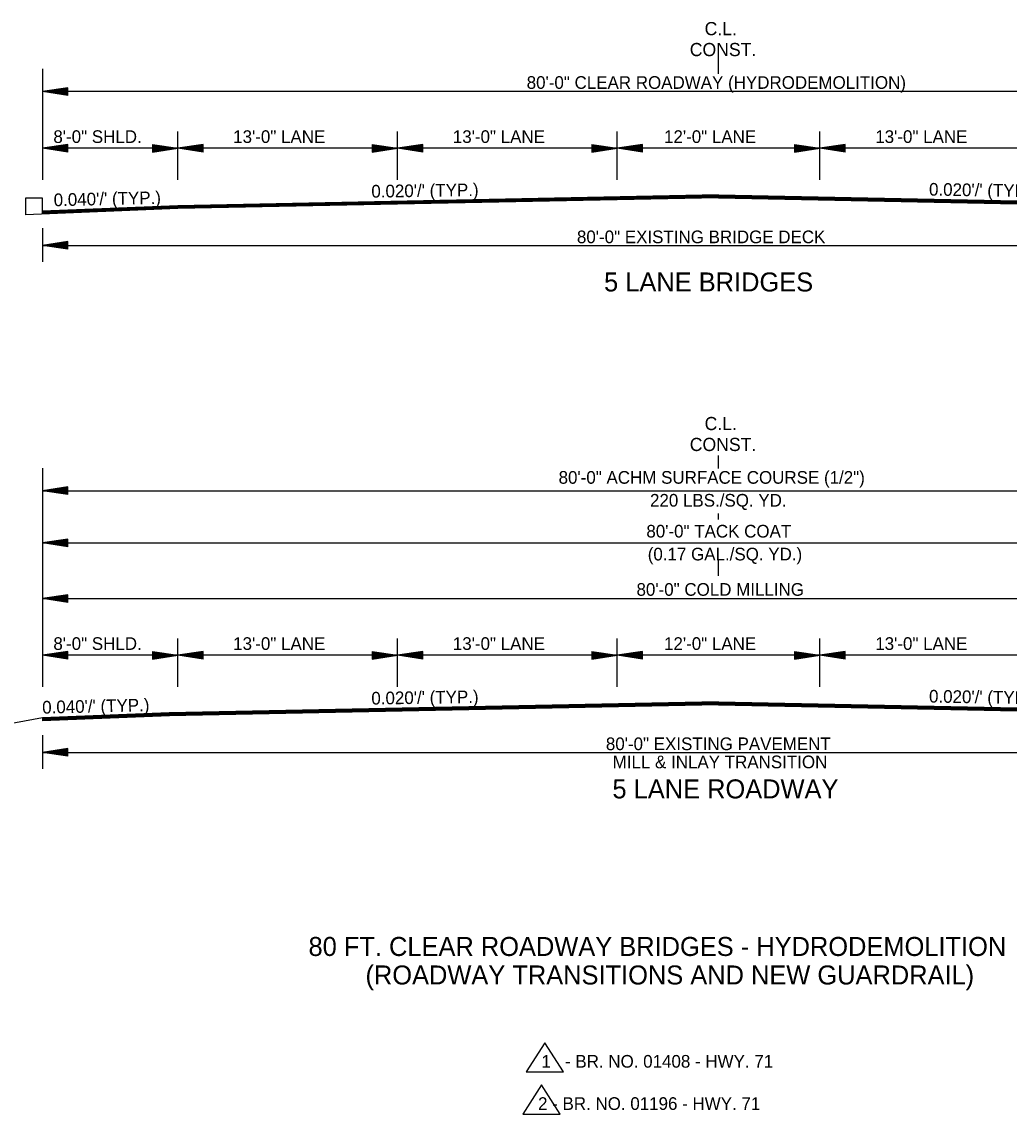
# Model space of a CAD drawing. Extents: x 542112 to 1930787, y -1968972 to 596640.
# Drawn here: x 544304 to 544888, y -1948133 to -1947487 of the extents above; entities that cross this region are included whole.
import ezdxf

# ---------------------------------------------------------------- set-up
doc = ezdxf.new("R2010")
doc.units = 0
doc.layers.add('R_Border', color=7, linetype='Continuous')
doc.layers.add('R_Draft', color=7, linetype='Continuous')

msp = doc.modelspace()

# ---------------------------------------------------------------- linework, layer by layer
at = {"layer": 'R_Border'}
for p, q in [((544315.93, -1947590.92), (544305.76, -1947590.92)), ((544305.76, -1947590.92), (544305.76, -1947600.74)), ((544315.93, -1947600.33), (544315.93, -1947590.92)), ((544613.21, -1948090.71), (544602.17, -1948108.01)), ((544624.25, -1948108.01), (544613.21, -1948090.71)), ((544602.17, -1948108.01), (544624.25, -1948108.01)), ((544611.21, -1948115.71), (544600.17, -1948133.01)), ((544622.25, -1948133.01), (544611.21, -1948115.71)), ((544600.17, -1948133.01), (544622.25, -1948133.01))]:
    msp.add_line(p, q, dxfattribs=at)
at = {"layer": 'R_Draft'}
for p, q in [((544715.93, -1947514.5), (544715.93, -1947505.2)), ((544715.93, -1947517.31), (544715.93, -1947509.46)), ((544315.93, -1947514.45), (544315.93, -1947580.11)), ((544330.93, -1947525.67), (544315.93, -1947527.92)), ((544330.93, -1947530.17), (544315.93, -1947527.92)), ((545115.93, -1947527.92), (544315.93, -1947527.92)), ((544330.93, -1947526.04), (544318.43, -1947527.92)), ((544330.93, -1947529.79), (544318.43, -1947527.92)), ((544330.93, -1947526.42), (544321.01, -1947527.92)), ((544330.93, -1947529.41), (544321.01, -1947527.92)), ((544330.93, -1947526.8), (544323.51, -1947527.92)), ((544330.93, -1947529.03), (544323.51, -1947527.92)), ((544330.93, -1947527.18), (544326.05, -1947527.92)), ((544330.93, -1947528.64), (544326.05, -1947527.92)), ((544330.93, -1947527.56), (544328.56, -1947527.92)), ((544330.93, -1947528.27), (544328.56, -1947527.92)), ((544330.93, -1947530.17), (544330.93, -1947525.67)), ((544395.93, -1947580.11), (544395.93, -1947551.56)), ((544525.93, -1947580.11), (544525.93, -1947551.56)), ((544655.93, -1947580.11), (544655.93, -1947551.56)), ((544775.93, -1947580.11), (544775.93, -1947551.56)), ((544330.93, -1947559.2), (544315.93, -1947561.45)), ((544330.93, -1947559.58), (544318.43, -1947561.45)), ((544330.93, -1947559.96), (544321.01, -1947561.45)), ((544330.93, -1947560.34), (544323.51, -1947561.45)), ((544330.93, -1947560.72), (544326.05, -1947561.45)), ((544330.93, -1947561.1), (544328.56, -1947561.45)), ((544330.93, -1947563.7), (544330.93, -1947559.2)), ((544380.93, -1947559.2), (544395.93, -1947561.45)), ((544380.93, -1947559.2), (544380.93, -1947563.7)), ((544380.93, -1947559.58), (544393.42, -1947561.45)), ((544380.93, -1947559.96), (544390.84, -1947561.45)), ((544380.93, -1947560.34), (544388.35, -1947561.45)), ((544380.93, -1947560.73), (544385.8, -1947561.45)), ((544380.93, -1947561.1), (544383.3, -1947561.45)), ((544410.93, -1947559.2), (544395.93, -1947561.45)), ((544410.93, -1947559.58), (544398.43, -1947561.45)), ((544410.93, -1947559.96), (544401.01, -1947561.45)), ((544410.93, -1947560.34), (544403.51, -1947561.45)), ((544410.93, -1947560.72), (544406.05, -1947561.45)), ((544410.93, -1947561.1), (544408.56, -1947561.45)), ((544410.93, -1947563.7), (544410.93, -1947559.2)), ((544510.93, -1947559.2), (544525.93, -1947561.45)), ((544510.93, -1947559.2), (544510.93, -1947563.7)), ((544510.93, -1947559.58), (544523.42, -1947561.45)), ((544510.93, -1947559.96), (544520.84, -1947561.45)), ((544510.93, -1947560.34), (544518.35, -1947561.45)), ((544510.93, -1947560.73), (544515.8, -1947561.45)), ((544510.93, -1947561.1), (544513.3, -1947561.45)), ((544540.93, -1947559.2), (544525.93, -1947561.45)), ((544540.93, -1947559.58), (544528.43, -1947561.45)), ((544540.93, -1947559.96), (544531.01, -1947561.45)), ((544540.93, -1947560.34), (544533.51, -1947561.45)), ((544540.93, -1947560.72), (544536.05, -1947561.45)), ((544540.93, -1947561.1), (544538.56, -1947561.45)), ((544540.93, -1947563.7), (544540.93, -1947559.2)), ((544640.93, -1947559.2), (544655.93, -1947561.45)), ((544640.93, -1947559.2), (544640.93, -1947563.7)), ((544640.93, -1947559.58), (544653.42, -1947561.45)), ((544640.93, -1947559.96), (544650.84, -1947561.45)), ((544640.93, -1947560.34), (544648.35, -1947561.45)), ((544640.93, -1947560.73), (544645.8, -1947561.45)), ((544640.93, -1947561.1), (544643.3, -1947561.45)), ((544670.93, -1947559.2), (544655.93, -1947561.45)), ((544670.93, -1947559.58), (544658.43, -1947561.45)), ((544670.93, -1947559.96), (544661.01, -1947561.45)), ((544670.93, -1947560.34), (544663.51, -1947561.45)), ((544670.93, -1947560.72), (544666.05, -1947561.45)), ((544670.93, -1947561.1), (544668.56, -1947561.45)), ((544670.93, -1947563.7), (544670.93, -1947559.2)), ((544760.93, -1947559.2), (544775.93, -1947561.45)), ((544760.93, -1947559.2), (544760.93, -1947563.7)), ((544760.93, -1947559.58), (544773.42, -1947561.45)), ((544760.93, -1947559.96), (544770.84, -1947561.45)), ((544760.93, -1947560.34), (544768.35, -1947561.45)), ((544760.93, -1947560.73), (544765.8, -1947561.45)), ((544760.93, -1947561.1), (544763.3, -1947561.45)), ((544790.93, -1947559.2), (544775.93, -1947561.45)), ((544790.93, -1947559.58), (544778.43, -1947561.45)), ((544790.93, -1947559.96), (544781.01, -1947561.45)), ((544790.93, -1947560.34), (544783.51, -1947561.45)), ((544790.93, -1947560.72), (544786.05, -1947561.45)), ((544790.93, -1947561.1), (544788.56, -1947561.45)), ((544790.93, -1947563.7), (544790.93, -1947559.2)), ((544395.93, -1947561.45), (544315.93, -1947561.45)), ((544330.93, -1947563.7), (544315.93, -1947561.45)), ((544330.93, -1947563.33), (544318.43, -1947561.45)), ((544330.93, -1947562.95), (544321.01, -1947561.45)), ((544330.93, -1947562.57), (544323.51, -1947561.45)), ((544330.93, -1947562.18), (544326.05, -1947561.45)), ((544330.93, -1947561.81), (544328.56, -1947561.45)), ((544380.93, -1947563.7), (544395.93, -1947561.45)), ((544380.93, -1947562.19), (544385.8, -1947561.45)), ((544380.93, -1947562.95), (544390.84, -1947561.45)), ((544380.93, -1947563.33), (544393.42, -1947561.45)), ((544380.93, -1947562.57), (544388.35, -1947561.45)), ((544380.93, -1947561.81), (544383.3, -1947561.45)), ((544525.93, -1947561.45), (544395.93, -1947561.45)), ((544410.93, -1947563.7), (544395.93, -1947561.45)), ((544410.93, -1947563.33), (544398.43, -1947561.45)), ((544410.93, -1947562.95), (544401.01, -1947561.45)), ((544410.93, -1947562.57), (544403.51, -1947561.45)), ((544410.93, -1947562.18), (544406.05, -1947561.45)), ((544410.93, -1947561.81), (544408.56, -1947561.45)), ((544510.93, -1947563.7), (544525.93, -1947561.45)), ((544510.93, -1947562.19), (544515.8, -1947561.45)), ((544510.93, -1947562.95), (544520.84, -1947561.45)), ((544510.93, -1947563.33), (544523.42, -1947561.45)), ((544510.93, -1947562.57), (544518.35, -1947561.45)), ((544510.93, -1947561.81), (544513.3, -1947561.45)), ((544655.93, -1947561.45), (544525.93, -1947561.45)), ((544540.93, -1947563.7), (544525.93, -1947561.45)), ((544540.93, -1947563.33), (544528.43, -1947561.45)), ((544540.93, -1947562.95), (544531.01, -1947561.45)), ((544540.93, -1947562.57), (544533.51, -1947561.45)), ((544540.93, -1947562.18), (544536.05, -1947561.45)), ((544540.93, -1947561.81), (544538.56, -1947561.45)), ((544640.93, -1947563.7), (544655.93, -1947561.45)), ((544640.93, -1947562.19), (544645.8, -1947561.45)), ((544640.93, -1947562.95), (544650.84, -1947561.45)), ((544640.93, -1947563.33), (544653.42, -1947561.45)), ((544640.93, -1947562.57), (544648.35, -1947561.45)), ((544640.93, -1947561.81), (544643.3, -1947561.45)), ((544775.93, -1947561.45), (544655.93, -1947561.45)), ((544670.93, -1947563.7), (544655.93, -1947561.45)), ((544670.93, -1947563.33), (544658.43, -1947561.45)), ((544670.93, -1947562.95), (544661.01, -1947561.45)), ((544670.93, -1947562.57), (544663.51, -1947561.45)), ((544670.93, -1947562.18), (544666.05, -1947561.45)), ((544670.93, -1947561.81), (544668.56, -1947561.45)), ((544760.93, -1947563.7), (544775.93, -1947561.45)), ((544760.93, -1947562.19), (544765.8, -1947561.45)), ((544760.93, -1947562.95), (544770.84, -1947561.45)), ((544760.93, -1947563.33), (544773.42, -1947561.45)), ((544760.93, -1947562.57), (544768.35, -1947561.45)), ((544760.93, -1947561.81), (544763.3, -1947561.45)), ((544905.93, -1947561.45), (544775.93, -1947561.45)), ((544790.93, -1947563.7), (544775.93, -1947561.45)), ((544790.93, -1947563.33), (544778.43, -1947561.45)), ((544790.93, -1947562.95), (544781.01, -1947561.45)), ((544790.93, -1947562.57), (544783.51, -1947561.45)), ((544790.93, -1947562.18), (544786.05, -1947561.45)), ((544790.93, -1947561.81), (544788.56, -1947561.45)), ((544715.93, -1947589.06), (544395.93, -1947595.46)), ((544715.94, -1947589.36), (544395.93, -1947595.76)), ((544715.94, -1947589.66), (544395.93, -1947596.06)), ((544715.95, -1947589.96), (544395.93, -1947596.36)), ((544715.95, -1947590.26), (544395.93, -1947596.66)), ((544715.96, -1947590.56), (544395.93, -1947596.96)), ((544715.96, -1947590.73), (544395.93, -1947597.13)), ((544715.9, -1947590.56), (545035.93, -1947596.96)), ((544715.9, -1947590.73), (545035.93, -1947597.13)), ((544715.91, -1947589.96), (545035.93, -1947596.36)), ((544715.91, -1947590.26), (545035.93, -1947596.66)), ((544715.92, -1947589.36), (545035.93, -1947595.76)), ((544715.92, -1947589.66), (545035.93, -1947596.06)), ((544715.93, -1947589.06), (545035.93, -1947595.46)), ((544395.93, -1947597.13), (544305.76, -1947600.74)), ((544395.93, -1947595.46), (544315.93, -1947598.66)), ((544395.93, -1947595.76), (544315.93, -1947598.96)), ((544395.93, -1947596.06), (544315.93, -1947599.26)), ((544395.93, -1947596.36), (544315.93, -1947599.56)), ((544395.93, -1947596.66), (544315.93, -1947599.86)), ((544395.93, -1947596.96), (544315.93, -1947600.16)), ((544315.93, -1947598.66), (544315.93, -1947600.33)), ((544315.93, -1947608.67), (544315.93, -1947628.67)), ((544330.93, -1947616.67), (544315.93, -1947618.92)), ((544315.93, -1947618.92), (545115.93, -1947618.92)), ((544330.93, -1947621.17), (544315.93, -1947618.92)), ((544330.93, -1947617.04), (544318.43, -1947618.92)), ((544330.93, -1947620.79), (544318.43, -1947618.92)), ((544330.93, -1947617.43), (544321.01, -1947618.92)), ((544330.93, -1947620.41), (544321.01, -1947618.92)), ((544330.93, -1947617.8), (544323.51, -1947618.92)), ((544330.93, -1947620.04), (544323.51, -1947618.92)), ((544330.93, -1947618.18), (544326.05, -1947618.92)), ((544330.93, -1947619.65), (544326.05, -1947618.92)), ((544330.93, -1947618.57), (544328.56, -1947618.92)), ((544330.93, -1947619.27), (544328.56, -1947618.92)), ((544330.93, -1947621.17), (544330.93, -1947616.67)), ((544715.93, -1947751.02), (544715.93, -1947743.16)), ((544315.93, -1947750.66), (544315.93, -1947880.11)), ((544330.93, -1947761.87), (544315.93, -1947764.12)), ((544315.93, -1947764.12), (545115.93, -1947764.12)), ((544330.93, -1947766.37), (544315.93, -1947764.12)), ((544330.93, -1947762.24), (544318.43, -1947764.12)), ((544330.93, -1947765.99), (544318.43, -1947764.12)), ((544330.93, -1947762.62), (544321.01, -1947764.12)), ((544330.93, -1947765.61), (544321.01, -1947764.12)), ((544330.93, -1947763), (544323.51, -1947764.12)), ((544330.93, -1947765.23), (544323.51, -1947764.12)), ((544330.93, -1947763.38), (544326.05, -1947764.12)), ((544330.93, -1947764.84), (544326.05, -1947764.12)), ((544330.93, -1947763.76), (544328.56, -1947764.12)), ((544330.93, -1947764.47), (544328.56, -1947764.12)), ((544330.93, -1947766.37), (544330.93, -1947761.87)), ((544715.93, -1947781.14), (544715.93, -1947777.47)), ((544330.93, -1947792.74), (544315.93, -1947794.99)), ((544330.93, -1947793.11), (544318.43, -1947794.99)), ((544330.93, -1947793.49), (544321.01, -1947794.99)), ((544330.93, -1947793.87), (544323.51, -1947794.99)), ((544330.93, -1947797.24), (544330.93, -1947792.74)), ((544315.93, -1947794.99), (545115.93, -1947794.99)), ((544330.93, -1947797.24), (544315.93, -1947794.99)), ((544330.93, -1947796.86), (544318.43, -1947794.99)), ((544330.93, -1947796.48), (544321.01, -1947794.99)), ((544330.93, -1947796.1), (544323.51, -1947794.99)), ((544330.93, -1947794.25), (544326.05, -1947794.99)), ((544330.93, -1947795.71), (544326.05, -1947794.99)), ((544330.93, -1947794.63), (544328.56, -1947794.99)), ((544330.93, -1947795.34), (544328.56, -1947794.99)), ((544715.93, -1947814.5), (544715.93, -1947805.2)), ((544330.93, -1947825.67), (544315.93, -1947827.92)), ((544330.93, -1947826.04), (544318.43, -1947827.92)), ((544330.93, -1947830.17), (544330.93, -1947825.67)), ((544315.93, -1947827.92), (545115.93, -1947827.92)), ((544330.93, -1947830.17), (544315.93, -1947827.92)), ((544330.93, -1947829.79), (544318.43, -1947827.92)), ((544330.93, -1947826.42), (544321.01, -1947827.92)), ((544330.93, -1947829.41), (544321.01, -1947827.92)), ((544330.93, -1947826.8), (544323.51, -1947827.92)), ((544330.93, -1947829.03), (544323.51, -1947827.92)), ((544330.93, -1947827.18), (544326.05, -1947827.92)), ((544330.93, -1947828.64), (544326.05, -1947827.92)), ((544330.93, -1947827.56), (544328.56, -1947827.92)), ((544330.93, -1947828.27), (544328.56, -1947827.92)), ((544395.93, -1947880.11), (544395.93, -1947851.56)), ((544525.93, -1947880.11), (544525.93, -1947851.56)), ((544655.93, -1947880.11), (544655.93, -1947851.56)), ((544775.93, -1947880.11), (544775.93, -1947851.56)), ((544330.93, -1947859.2), (544315.93, -1947861.45)), ((544395.93, -1947861.45), (544315.93, -1947861.45)), ((544330.93, -1947863.7), (544315.93, -1947861.45)), ((544330.93, -1947859.58), (544318.43, -1947861.45)), ((544330.93, -1947863.33), (544318.43, -1947861.45)), ((544330.93, -1947859.96), (544321.01, -1947861.45)), ((544330.93, -1947862.95), (544321.01, -1947861.45)), ((544330.93, -1947860.34), (544323.51, -1947861.45)), ((544330.93, -1947862.57), (544323.51, -1947861.45)), ((544330.93, -1947860.72), (544326.05, -1947861.45)), ((544330.93, -1947862.18), (544326.05, -1947861.45)), ((544330.93, -1947861.1), (544328.56, -1947861.45)), ((544330.93, -1947861.81), (544328.56, -1947861.45)), ((544330.93, -1947863.7), (544330.93, -1947859.2)), ((544380.93, -1947859.2), (544395.93, -1947861.45)), ((544380.93, -1947859.2), (544380.93, -1947863.7)), ((544380.93, -1947859.58), (544393.42, -1947861.45)), ((544380.93, -1947859.96), (544390.84, -1947861.45)), ((544380.93, -1947860.34), (544388.35, -1947861.45)), ((544380.93, -1947860.73), (544385.8, -1947861.45)), ((544380.93, -1947861.1), (544383.3, -1947861.45)), ((544380.93, -1947863.7), (544395.93, -1947861.45)), ((544380.93, -1947862.19), (544385.8, -1947861.45)), ((544380.93, -1947862.95), (544390.84, -1947861.45)), ((544380.93, -1947863.33), (544393.42, -1947861.45)), ((544380.93, -1947862.57), (544388.35, -1947861.45)), ((544380.93, -1947861.81), (544383.3, -1947861.45)), ((544410.93, -1947859.2), (544395.93, -1947861.45)), ((544525.93, -1947861.45), (544395.93, -1947861.45)), ((544410.93, -1947863.7), (544395.93, -1947861.45)), ((544410.93, -1947859.58), (544398.43, -1947861.45)), ((544410.93, -1947863.33), (544398.43, -1947861.45)), ((544410.93, -1947859.96), (544401.01, -1947861.45)), ((544410.93, -1947862.95), (544401.01, -1947861.45)), ((544410.93, -1947860.34), (544403.51, -1947861.45)), ((544410.93, -1947862.57), (544403.51, -1947861.45)), ((544410.93, -1947860.72), (544406.05, -1947861.45)), ((544410.93, -1947862.18), (544406.05, -1947861.45)), ((544410.93, -1947861.1), (544408.56, -1947861.45)), ((544410.93, -1947861.81), (544408.56, -1947861.45)), ((544410.93, -1947863.7), (544410.93, -1947859.2)), ((544510.93, -1947859.2), (544525.93, -1947861.45)), ((544510.93, -1947859.2), (544510.93, -1947863.7)), ((544510.93, -1947859.58), (544523.42, -1947861.45)), ((544510.93, -1947859.96), (544520.84, -1947861.45)), ((544510.93, -1947860.34), (544518.35, -1947861.45)), ((544510.93, -1947860.73), (544515.8, -1947861.45)), ((544510.93, -1947861.1), (544513.3, -1947861.45)), ((544510.93, -1947863.7), (544525.93, -1947861.45)), ((544510.93, -1947862.19), (544515.8, -1947861.45)), ((544510.93, -1947862.95), (544520.84, -1947861.45)), ((544510.93, -1947863.33), (544523.42, -1947861.45)), ((544510.93, -1947862.57), (544518.35, -1947861.45)), ((544510.93, -1947861.81), (544513.3, -1947861.45)), ((544540.93, -1947859.2), (544525.93, -1947861.45)), ((544655.93, -1947861.45), (544525.93, -1947861.45)), ((544540.93, -1947863.7), (544525.93, -1947861.45)), ((544540.93, -1947859.58), (544528.43, -1947861.45)), ((544540.93, -1947863.33), (544528.43, -1947861.45)), ((544540.93, -1947859.96), (544531.01, -1947861.45)), ((544540.93, -1947862.95), (544531.01, -1947861.45)), ((544540.93, -1947860.34), (544533.51, -1947861.45)), ((544540.93, -1947862.57), (544533.51, -1947861.45)), ((544540.93, -1947860.72), (544536.05, -1947861.45)), ((544540.93, -1947862.18), (544536.05, -1947861.45)), ((544540.93, -1947861.1), (544538.56, -1947861.45)), ((544540.93, -1947861.81), (544538.56, -1947861.45)), ((544540.93, -1947863.7), (544540.93, -1947859.2)), ((544640.93, -1947859.2), (544655.93, -1947861.45)), ((544640.93, -1947859.2), (544640.93, -1947863.7)), ((544640.93, -1947859.58), (544653.42, -1947861.45)), ((544640.93, -1947859.96), (544650.84, -1947861.45)), ((544640.93, -1947860.34), (544648.35, -1947861.45)), ((544640.93, -1947860.73), (544645.8, -1947861.45)), ((544640.93, -1947861.1), (544643.3, -1947861.45)), ((544640.93, -1947863.7), (544655.93, -1947861.45)), ((544640.93, -1947862.19), (544645.8, -1947861.45)), ((544640.93, -1947862.95), (544650.84, -1947861.45)), ((544640.93, -1947863.33), (544653.42, -1947861.45)), ((544640.93, -1947862.57), (544648.35, -1947861.45)), ((544640.93, -1947861.81), (544643.3, -1947861.45)), ((544670.93, -1947859.2), (544655.93, -1947861.45)), ((544775.93, -1947861.45), (544655.93, -1947861.45)), ((544670.93, -1947863.7), (544655.93, -1947861.45)), ((544670.93, -1947859.58), (544658.43, -1947861.45)), ((544670.93, -1947863.33), (544658.43, -1947861.45)), ((544670.93, -1947859.96), (544661.01, -1947861.45)), ((544670.93, -1947862.95), (544661.01, -1947861.45)), ((544670.93, -1947860.34), (544663.51, -1947861.45)), ((544670.93, -1947862.57), (544663.51, -1947861.45)), ((544670.93, -1947860.72), (544666.05, -1947861.45)), ((544670.93, -1947862.18), (544666.05, -1947861.45)), ((544670.93, -1947861.1), (544668.56, -1947861.45)), ((544670.93, -1947861.81), (544668.56, -1947861.45)), ((544670.93, -1947863.7), (544670.93, -1947859.2)), ((544760.93, -1947859.2), (544775.93, -1947861.45)), ((544760.93, -1947859.2), (544760.93, -1947863.7)), ((544760.93, -1947859.58), (544773.42, -1947861.45)), ((544760.93, -1947859.96), (544770.84, -1947861.45)), ((544760.93, -1947860.34), (544768.35, -1947861.45)), ((544760.93, -1947860.73), (544765.8, -1947861.45)), ((544760.93, -1947861.1), (544763.3, -1947861.45)), ((544760.93, -1947863.7), (544775.93, -1947861.45)), ((544760.93, -1947862.19), (544765.8, -1947861.45)), ((544760.93, -1947862.95), (544770.84, -1947861.45)), ((544760.93, -1947863.33), (544773.42, -1947861.45)), ((544760.93, -1947862.57), (544768.35, -1947861.45)), ((544760.93, -1947861.81), (544763.3, -1947861.45)), ((544790.93, -1947859.2), (544775.93, -1947861.45)), ((544905.93, -1947861.45), (544775.93, -1947861.45)), ((544790.93, -1947863.7), (544775.93, -1947861.45)), ((544790.93, -1947859.58), (544778.43, -1947861.45)), ((544790.93, -1947863.33), (544778.43, -1947861.45)), ((544790.93, -1947859.96), (544781.01, -1947861.45)), ((544790.93, -1947862.95), (544781.01, -1947861.45)), ((544790.93, -1947860.34), (544783.51, -1947861.45)), ((544790.93, -1947862.57), (544783.51, -1947861.45)), ((544790.93, -1947860.72), (544786.05, -1947861.45)), ((544790.93, -1947862.18), (544786.05, -1947861.45)), ((544790.93, -1947861.1), (544788.56, -1947861.45)), ((544790.93, -1947861.81), (544788.56, -1947861.45)), ((544790.93, -1947863.7), (544790.93, -1947859.2)), ((544715.93, -1947889.06), (544390.93, -1947895.56)), ((544715.94, -1947889.36), (544390.94, -1947895.86)), ((544715.94, -1947889.66), (544390.94, -1947896.16)), ((544715.95, -1947889.96), (544390.95, -1947896.46)), ((544715.95, -1947890.26), (544390.95, -1947896.76)), ((544715.96, -1947890.56), (544390.96, -1947897.06)), ((544715.96, -1947890.73), (544390.96, -1947897.23)), ((544715.9, -1947890.56), (545035.93, -1947896.96)), ((544715.9, -1947890.73), (545035.93, -1947897.13)), ((544715.91, -1947889.96), (545035.93, -1947896.36)), ((544715.91, -1947890.26), (545035.93, -1947896.66)), ((544715.92, -1947889.36), (545035.93, -1947895.76)), ((544715.92, -1947889.66), (545035.93, -1947896.06)), ((544715.93, -1947889.06), (545035.93, -1947895.46)), ((544390.93, -1947895.56), (544315.93, -1947898.56)), ((544390.94, -1947895.86), (544315.93, -1947898.86)), ((544390.95, -1947896.16), (544315.93, -1947899.16)), ((544390.97, -1947896.46), (544315.93, -1947899.46)), ((544390.98, -1947896.76), (544315.93, -1947899.76)), ((544390.99, -1947897.06), (544315.93, -1947900.06)), ((544391, -1947897.23), (544315.93, -1947900.23)), ((544315.93, -1947898.56), (544215.86, -1947916.94)), ((544315.93, -1947898.56), (544315.93, -1947900.23)), ((544315.93, -1947908.67), (544315.93, -1947928.67)), ((544330.93, -1947916.67), (544315.93, -1947918.92)), ((544330.93, -1947921.17), (544330.93, -1947916.67)), ((544315.93, -1947918.92), (545115.93, -1947918.92)), ((544330.93, -1947921.17), (544315.93, -1947918.92)), ((544330.93, -1947917.04), (544318.43, -1947918.92)), ((544330.93, -1947920.79), (544318.43, -1947918.92)), ((544330.93, -1947917.43), (544321.01, -1947918.92)), ((544330.93, -1947920.41), (544321.01, -1947918.92)), ((544330.93, -1947917.8), (544323.51, -1947918.92)), ((544330.93, -1947920.04), (544323.51, -1947918.92)), ((544330.93, -1947918.18), (544326.05, -1947918.92)), ((544330.93, -1947919.65), (544326.05, -1947918.92)), ((544330.93, -1947918.57), (544328.56, -1947918.92)), ((544330.93, -1947919.27), (544328.56, -1947918.92))]:
    msp.add_line(p, q, dxfattribs=at)

# ---------------------------------------------------------------- texts
for s, height, p in [('C.L.', 7.8, (544707.74, -1947494.52)), ('CONST.', 7.8, (544698.96, -1947506.89)), ('80\'-0" CLEAR ROADWAY (HYDRODEMOLITION)', 7.5, (544602.45, -1947526.25)), ('8\'-0" SHLD.', 7.5, (544322.33, -1947558.28)), ('13\'-0" LANE', 7.5, (544428.74, -1947558.28)), ('13\'-0" LANE', 7.5, (544558.74, -1947558.28)), ('12\'-0" LANE', 7.5, (544683.74, -1947558.28)), ('13\'-0" LANE', 7.5, (544808.74, -1947558.28)), ('80\'-0" EXISTING BRIDGE DECK', 7.5, (544632.19, -1947617.6)), ('5 LANE BRIDGES', 11.25, (544648.25, -1947646.16)), ('C.L.', 7.8, (544707.74, -1947728.22)), ('CONST.', 7.8, (544698.96, -1947740.59)), ('80\'-0" ACHM SURFACE COURSE (1/2")', 7.5, (544621.34, -1947759.95)), ('220 LBS./SQ. YD. ', 7.5, (544675.44, -1947773.49)), ('80\'-0" TACK COAT', 7.5, (544673.28, -1947791.78)), ('(0.17 GAL./SQ. YD.)', 7.5, (544674.08, -1947805.33)), ('80\'-0" COLD MILLING', 7.5, (544667.44, -1947826.25)), ('8\'-0" SHLD.', 7.5, (544322.33, -1947858.28)), ('13\'-0" LANE', 7.5, (544428.74, -1947858.28)), ('13\'-0" LANE', 7.5, (544558.74, -1947858.28)), ('12\'-0" LANE', 7.5, (544683.74, -1947858.28)), ('13\'-0" LANE', 7.5, (544808.74, -1947858.28)), ('80\'-0" EXISTING PAVEMENT', 7.5, (544649.31, -1947917.6)), ('MILL & INLAY TRANSITION', 7.5, (544653.32, -1947928.32)), ('5 LANE ROADWAY', 11.25, (544653.2, -1947946.16)), ('80 FT. CLEAR ROADWAY BRIDGES - HYDRODEMOLITION', 11.25, (544473.34, -1948039.4)), ('(ROADWAY TRANSITIONS AND NEW GUARDRAIL)', 11.25, (544507.04, -1948056.27)), ('1   - BR. NO. 01408 - HWY. 71', 7.5, (544611.21, -1948105.5)), ('2 - BR. NO. 01196 - HWY. 71', 7.5, (544609.17, -1948130.5))]:
    msp.add_text(s, height=height, dxfattribs=at).set_placement(p)
for s, rotation, p in [("0.040'/' (TYP.)", 1.31838, (544322.6, -1947595.74)), ("0.020'/' (TYP.)", 0.87191, (544510.57, -1947590.65)), ("0.020'/' (TYP.)", 359.12809, (544840.51, -1947589.42)), ("0.020'/' (TYP.)", 0.87191, (544510.57, -1947890.65)), ("0.020'/' (TYP.)", 359.12809, (544840.51, -1947889.42)), ("0.040'/' (TYP.)", 1.31838, (544315.81, -1947896.01))]:
    msp.add_text(s, height=7.5, rotation=rotation, dxfattribs=at).set_placement(p)

doc.saveas('drawing.dxf')
